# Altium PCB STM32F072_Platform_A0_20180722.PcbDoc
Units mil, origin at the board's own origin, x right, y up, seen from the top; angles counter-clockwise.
Board outline 3937.01 x 3937.01 mil, 2 copper layers (Top Layer, Bottom Layer); 126 components, 110 nets, 444 pads, 50 vias.
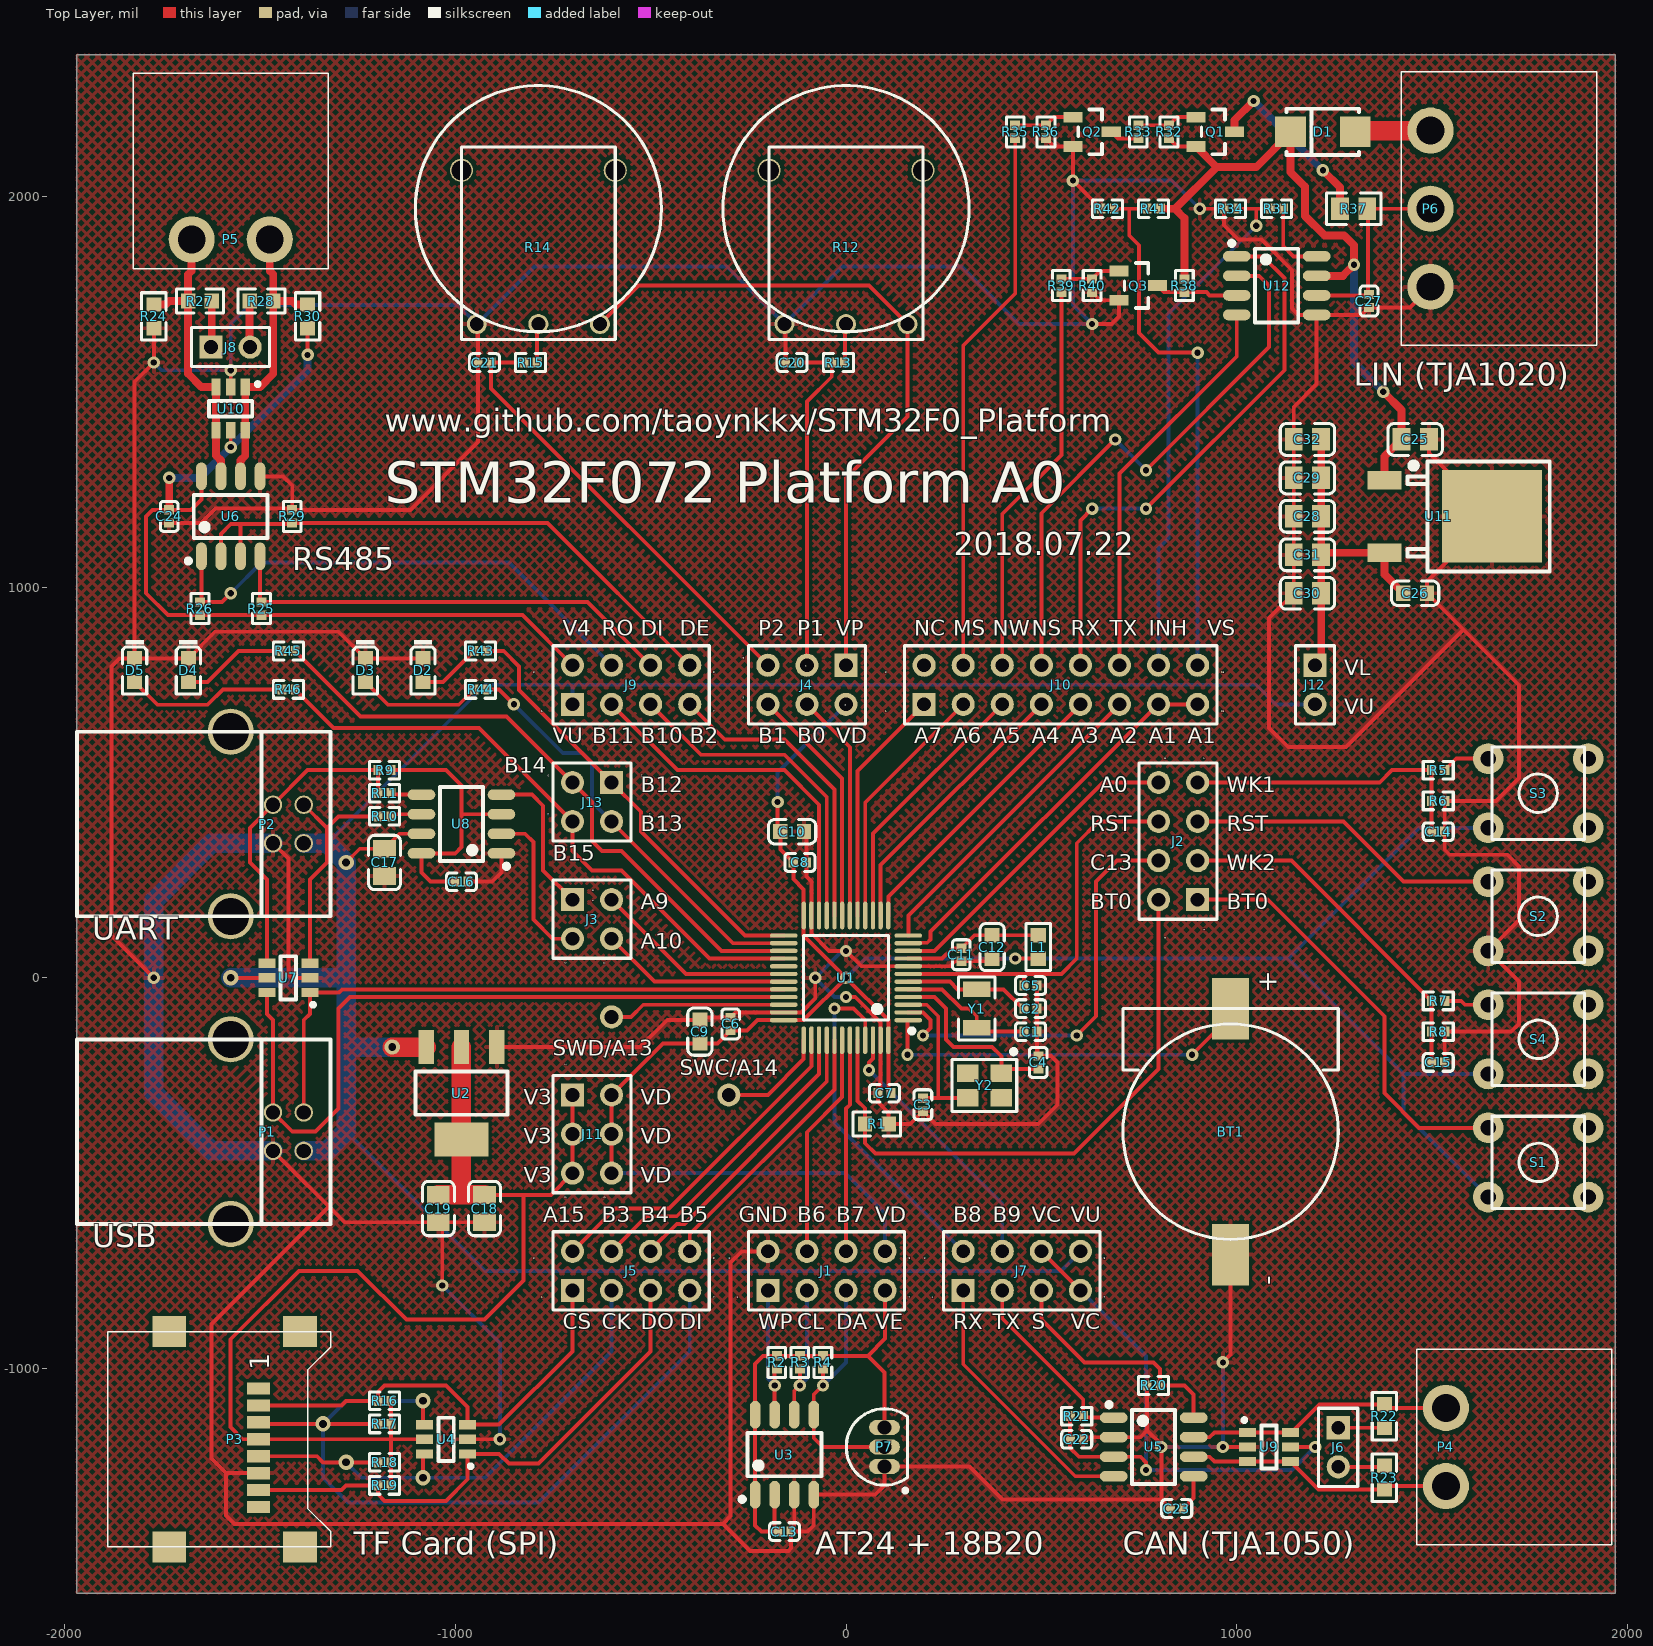
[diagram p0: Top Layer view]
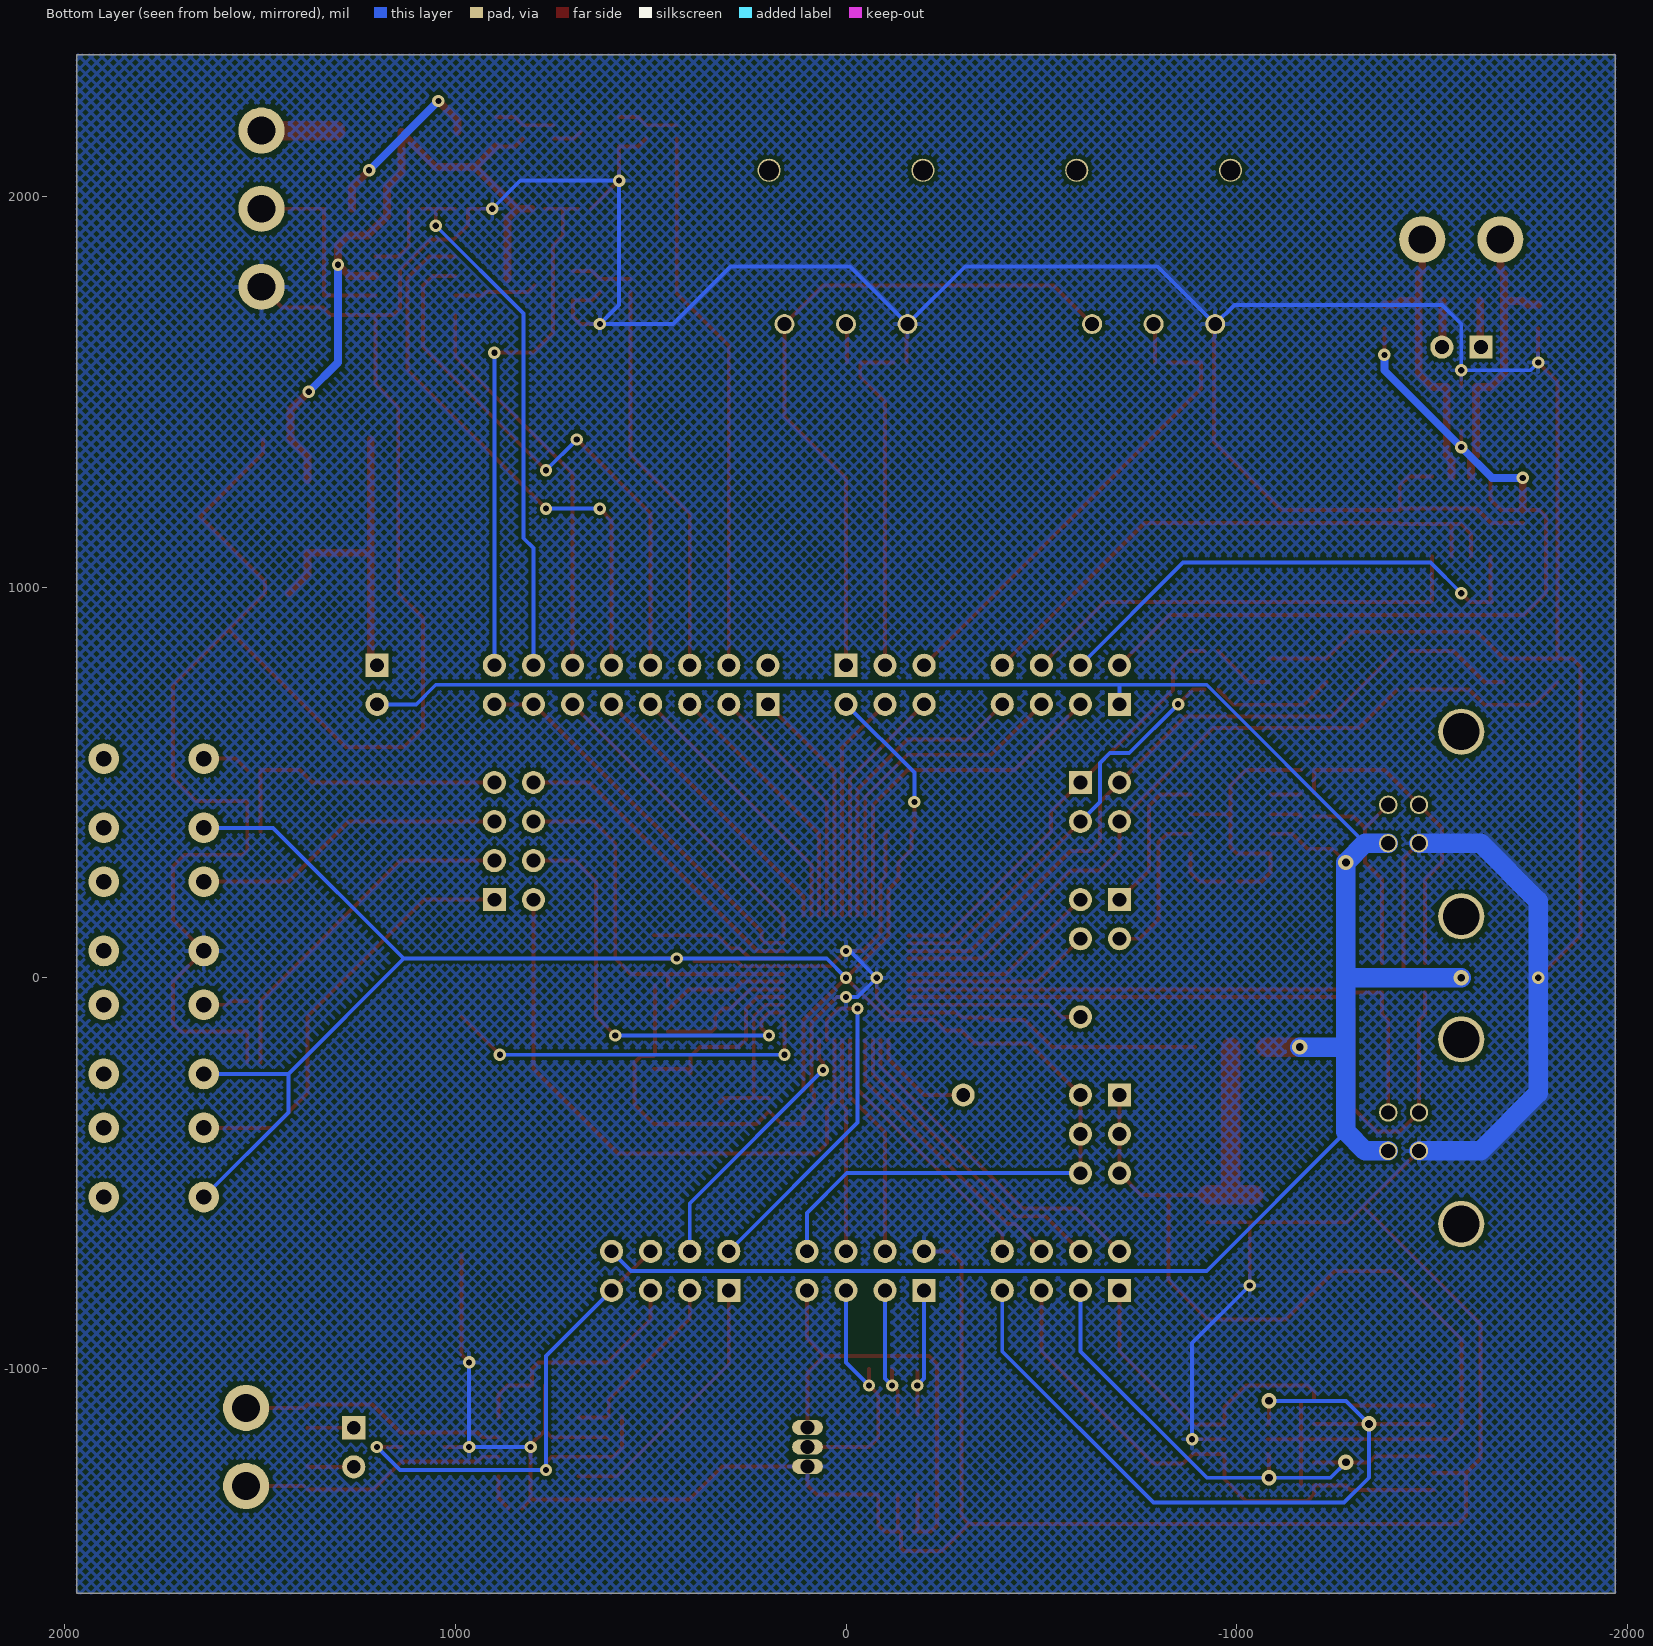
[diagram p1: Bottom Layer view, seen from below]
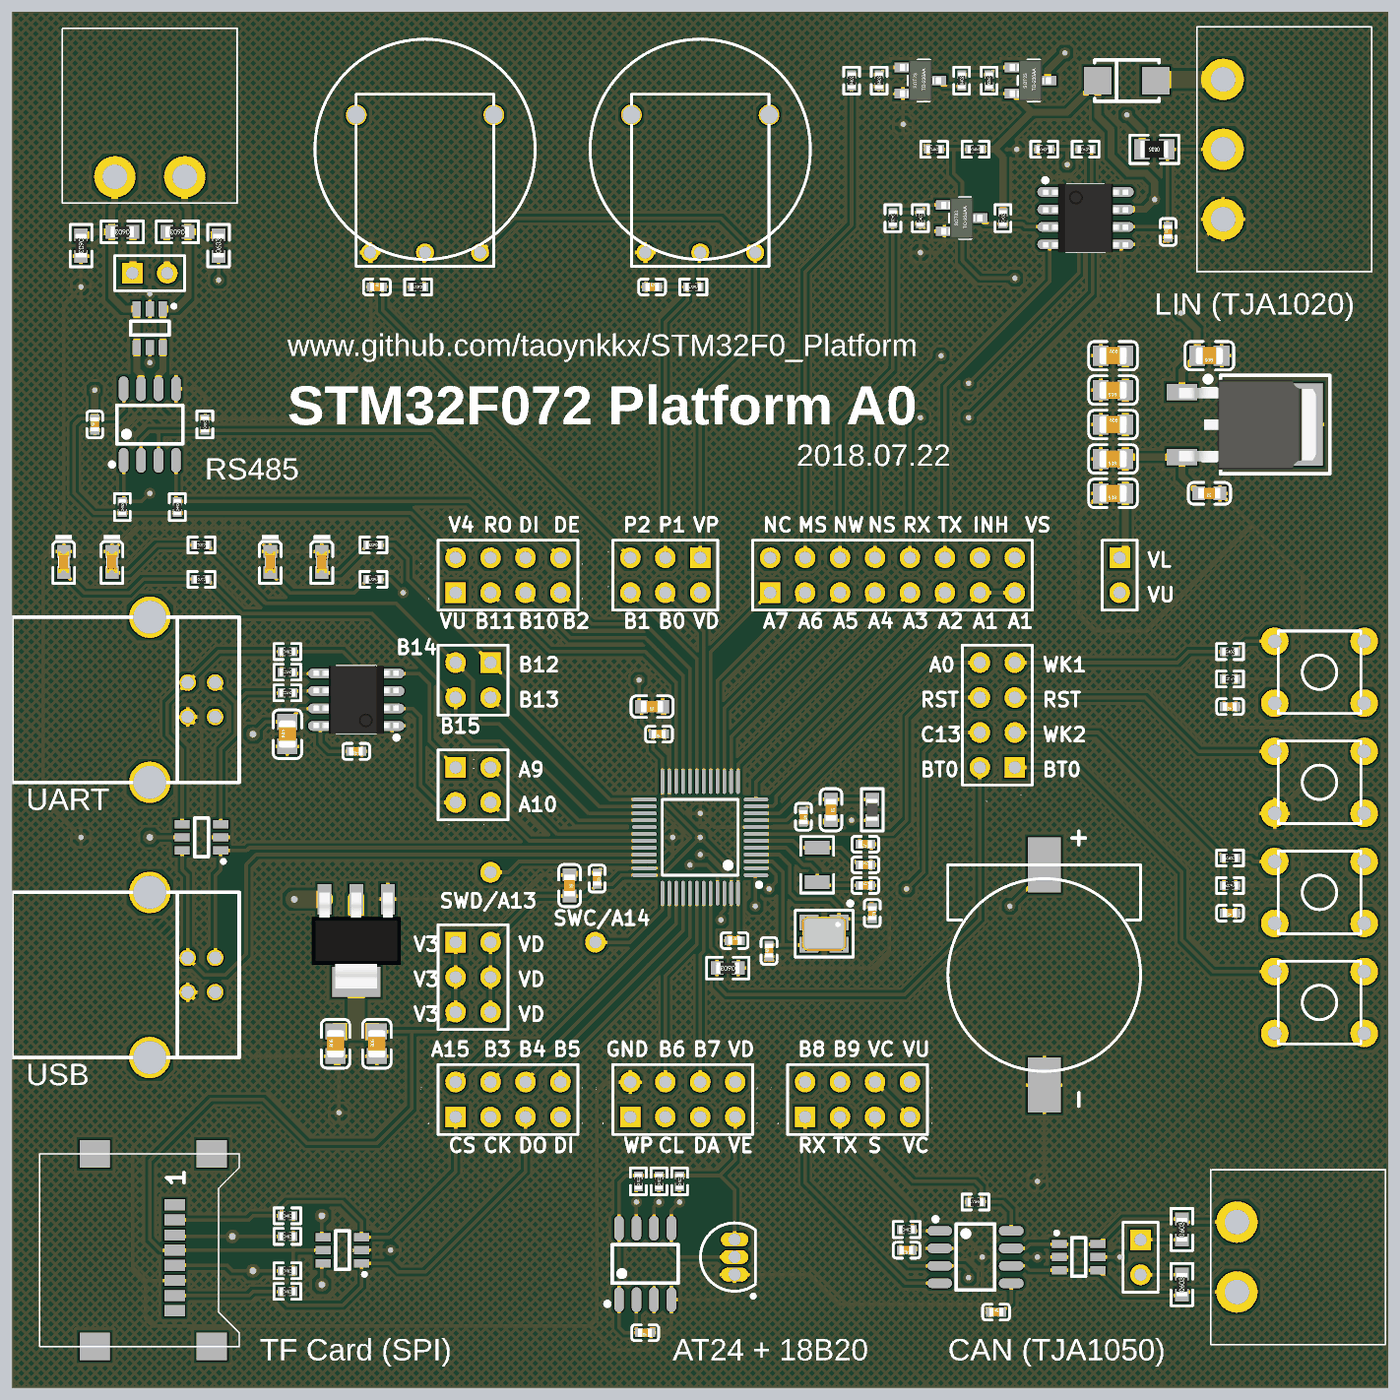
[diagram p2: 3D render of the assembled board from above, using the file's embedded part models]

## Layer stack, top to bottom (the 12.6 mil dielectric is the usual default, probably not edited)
Top Layer: signal copper 1.4
Dielectric: dielectric 12.6, FR-4, Dk 4.8
Bottom Layer: signal copper 1.4

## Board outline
-1968.5,-1574.8 -1968.5,2362.2 1968.5,2362.2 1968.5,-1574.8

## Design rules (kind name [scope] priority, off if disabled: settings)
Clearance [All] p1: gap=8
MinimumSolderMaskSliver [All] p1 off: minsoldermaskwidth=10
PolygonConnect [All] p1: connectstyle=Relief reliefconductorwidth=10 reliefentries=4 polygonreliefangle="90 Angle"
RoomDefinition LED [InComponentClass('LED')] p1: confinementstyle=ConfineIn formatcopy=TRUE lockcomponents=TRUE outline -2047.24,590.55 -787.4,590.55 -787.4,984.25 -2047.24,984.25
RoomDefinition LIN [InComponentClass('LIN')] p2: confinementstyle=ConfineIn formatcopy=TRUE lockcomponents=TRUE outline 393.7,787.4 1968.5,787.4 1968.5,2362.2 393.7,2362.2
RoomDefinition 485 [InComponentClass('485')] p3: confinementstyle=ConfineIn formatcopy=TRUE lockcomponents=TRUE outline -1181.1,787.4 -1181.1,2362.2 -1968.5,2362.2 -1968.5,787.4
RoomDefinition CAN [InComponentClass('CAN')] p4: confinementstyle=ConfineIn formatcopy=TRUE lockcomponents=TRUE outline 393.7,-1476.38 1968.5,-1476.38 1968.5,-925.2 393.7,-925.2
RoomDefinition SPI [InComponentClass('SPI')] p5: confinementstyle=ConfineIn formatcopy=TRUE lockcomponents=TRUE outline -1968.5,-1574.8 -590.55,-1574.8 -590.55,-787.4 -1968.5,-787.4
RoomDefinition ADC [InComponentClass('ADC')] p6: confinementstyle=ConfineIn formatcopy=TRUE lockcomponents=TRUE outline -1181.1,1377.95 393.7,1377.95 393.7,2362.2 -1181.1,2362.2
RoomDefinition USB [InComponentClass('USB')] p7: confinementstyle=ConfineIn formatcopy=TRUE lockcomponents=TRUE outline -787.4,-787.4 -787.4,787.4 -2165.35,787.4 -2165.35,-787.4
RoomDefinition BTN [InComponentClass('BTN')] p8: confinementstyle=ConfineIn formatcopy=TRUE lockcomponents=TRUE outline 1377.95,-629.92 1968.5,-629.92 1968.5,629.92 1377.95,629.92
RoomDefinition MCU [InComponentClass('MCU')] p9: confinementstyle=ConfineIn formatcopy=TRUE lockcomponents=TRUE outline -590.55,-590.55 590.55,-590.55 590.55,590.55 -590.55,590.55
RoomDefinition EEPROM [InComponentClass('EEPROM')] p10: confinementstyle=ConfineIn formatcopy=TRUE lockcomponents=TRUE outline -295.28,-905.51 -295.28,-1476.38 196.85,-1476.38 196.85,-905.51
RoutingVias [All] p1: holewidth=28 width=50 viastyle="Through Hole" minholewidth=28 minwidth=50 maxholewidth=28 maxwidth=50
SilkToSilkClearance [All] p1 off: silktosilkclearance=10
SilkscreenOverComponentPads [All] p1 off: minsilkscreentomaskgap=10
SolderMaskExpansion [All] p1: expansion=4
Width [All] p1: maxlimit=50 minlimit=10 preferedwidth=10
25 further rules are at their usual default settings.

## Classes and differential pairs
component class LED: D2 D3 D4 D5 R43 R44 R45 R46
component class LIN: C25 C26 C27 C28 C29 C30 C31 C32 D1 P6 Q1 Q2 Q3 R31 R32 R33 R34 R35 R36 R37 R38 R39 R40 R41 R42 U11 U12
component class CAN: C22 C23 J6 P4 R20 R21 R22 R23 U5 U9
component class ADC: C20 C21 R12 R13 R14 R15
component class STM32F072_Platform: BT1 J1 J2 J3 J4 J5 J7 J9 J10 J11 J12 J13
component class USB: C16 C17 C18 C19 P1 P2 R9 R10 R11 U2 U7 U8
component class BTN: C14 C15 R5 R6 R7 R8 S1 S2 S3 S4
component class EEPROM: C13 P7 R2 R3 R4 U3
component class MCU: C1 C2 C3 C4 C5 C6 C7 C8 C9 C10 C11 C12 L1 R1 U1 Y1 Y2
component class SPI: P3 R16 R17 R18 R19 U4
component class 485: C24 J8 P5 R24 R25 R26 R27 R28 R29 R30 U6 U10

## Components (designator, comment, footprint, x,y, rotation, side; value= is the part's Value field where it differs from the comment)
BT1 "Battery" CR1220 984.25,-393.7 r90 top
C1 "12pF (120) 5% 50V" 0402_C 472.44,-137.8 r0 top
C2 "12pF (120) 5% 50V" 0402_C 472.44,-78.74 r0 top
C3 "20pF (200) 5% 50V" 0402_C 196.85,-324.8 r90 top
C4 "20pF (200) 5% 50V" 0402_C 492.13,-216.54 r270 top
C5 "100nF (104) 10% 16V" 0402_C 472.44,-19.69 r180 top
C6 "100nF (104) 10% 16V" 0402_C -295.28,-118.11 r270 top
C7 "100nF (104) 10% 16V" 0402_C 98.43,-295.28 r0 top
C8 "100nF (104) 10% 16V" 0402_C -118.11,295.28 r180 top
C9 "4.7uF (475) 10% 16V" 0603_C -374.02,-137.8 r270 top
C10 "4.7uF (475) 10% 16V" 0603_C -137.8,374.02 r180 top
C11 "10nF (103) 10% 50V" 0402_C 295.28,59.06 r270 top
C12 "1uF (105) 10% 50V" 0603_C 374.02,78.74 r270 top
C13 "100nF (104) 10% 16V" 0402_C -157.48,-1417.32 r180 top
C14 "100nF (104) 10% 16V" 0402_C 1515.75,374.02 r180 top
C15 "100nF (104) 10% 16V" 0402_C 1515.75,-216.54 r180 top
C16 "100nF (104) 10% 16V" 0402_C -984.25,246.06 r180 top
C17 "10uF (106) 10% 25V" 0805_C -1181.1,295.28 r90 top
C18 "10uF (106) 10% 25V" 0805_C -925.2,-590.55 r90 top
C19 "10uF (106) 10% 25V" 0805_C -1043.31,-590.55 r90 top
C20 "100nF (104) 10% 16V" 0402_C -137.8,1574.8 r0 top
C21 "100nF (104) 10% 16V" 0402_C -925.2,1574.8 r0 top
C22 "100nF (104) 10% 16V" 0402_C 590.55,-1181.1 r180 top
C23 "100nF (104) 10% 16V" 0402_C 846.46,-1358.27 r0 top
C24 "100nF (104) 10% 16V" 0402_C -1732.28,1181.1 r90 top
C25 "2.2uF (225) 20% 50V" 0805_C 1456.69,1377.95 r180 top
C26 "1uF (105) 10% 50V" 0603_C 1456.69,984.25 r180 top
C27 "220pF (221) 10% 50V" 0402_C 1338.58,1732.28 r90 top
C28 "22uF (226) 20% 25V" 0805_C 1181.1,1181.1 r0 top
C29 "22uF (226) 20% 25V" 0805_C 1181.1,1279.53 r180 top
C30 "22uF (226) 20% 25V" 0805_C 1181.1,984.25 r180 top
C31 "22uF (226) 20% 25V" 0805_C 1181.1,1082.68 r180 top
C32 "22uF (226) 20% 25V" 0805_C 1181.1,1377.95 r0 top
D1 "M7" SMA(DO-214AC)_S1 1220.47,2165.35 r0 top
D2 "红灯 0603" 0603_LED_S1 -1082.68,787.4 r270 top
D3 "绿灯 0603" 0603_LED_S1 -1230.32,787.4 r270 top
D4 "蓝灯 0603" 0603_LED_S1 -1683.07,787.4 r270 top
D5 "黄灯 0603" 0603_LED_S1 -1820.87,787.4 r270 top
J1 "EEPROM" HDR2X4 -200,-800 r0 top
J2 "BUTTON" HDR2X4 900,200 r90 top
J3 "USART1" HDR2X2 -700,200 r270 top
J4 "POTMETER" HDR2X3 0,800 r180 top
J5 "TFCard" HDR2X4 -700,-800 r0 top
J6 "TERM" HDR1X2 1259.84,-1151.57 r270 top
J7 "CAN" HDR2X4 300,-800 r0 top
J8 "TERM_485" HDR1X2 -1625,1614.17 r0 top
J9 "485" HDR2X4 -700,700 r0 top
J10 "LIN" HDR2X8 200,700 r0 top
J11 "VDD" HDR2X3 -700,-300 r270 top
J12 "V5" HDR1X2 1200,800 r270 top
J13 "LED" HDR2X2 -600,500 r180 top
L1 "47nH" 0603_L 492.13,78.74 r90 top
P1 "USB_ST" USB-B/Female -1574.8,-393.7 r270 top
P2 "USB_PL" USB-B/Female -1574.8,393.7 r270 top
P3 "TFCard" TF002 -1870.08,-1181.1 r90 top
P4 "CAN" WJ2EDGRC-5.08-2PxxR 1535.43,-1200.79 r90 top
P5 "485" WJ2EDGRC-5.08-2PxxR -1574.8,1889.76 r180 top
P6 "LIN" WJ2EDGRC-5.08-3PxxR 1496.06,1968.5 r90 top
P7 "DS18B20" TO-92A 98.43,-1200.79 r0 top
Q1 "MMBT5401 2L" SOT-23(SOT-23-3) 944.88,2165.35 r180 top
Q2 "MMBT5551  G1" SOT-23(SOT-23-3) 629.92,2165.35 r180 top
Q3 "SS8050 Y1" SOT-23(SOT-23-3) 748.03,1771.65 r180 top
R1 "10KΩ (1002) ±1%" 0603_R 78.74,-374.02 r180 top
R2 "10KΩ (1002) ±1%" 0402_R -177.17,-984.25 r90 top
R3 "4.7KΩ (4701) ±1%" 0402_R -118.11,-984.25 r90 top
R4 "4.7KΩ (4701) ±1%" 0402_R -59.06,-984.25 r90 top
R5 "1KΩ (1001) ±1%" 0402_R 1515.75,531.5 r0 top
R6 "10KΩ (1002) ±1%" 0402_R 1515.75,452.76 r180 top
R7 "1KΩ (1001) ±1%" 0402_R 1515.75,-59.06 r0 top
R8 "10KΩ (1002) ±1%" 0402_R 1515.75,-137.8 r180 top
R9 "1.5KΩ (1501) ±1%" 0402_R -1181.1,531.5 r0 top
R10 "22Ω (22R0) ±1%" 0402_R -1181.1,413.39 r180 top
R11 "22Ω (22R0) ±1%" 0402_R -1181.1,472.44 r180 top
R12 "10K" AIN16 0,1968.5 r0 top
R13 "100Ω (1000) ±1%" 0402_R -19.69,1574.8 r180 top
R14 "10K" AIN16 -787.4,1968.5 r0 top
R15 "100Ω (1000) ±1%" 0402_R -807.09,1574.8 r180 top
R16 "10KΩ (1002) ±1%" 0402_R -1181.1,-1082.68 r0 top
R17 "10KΩ (1002) ±1%" 0402_R -1181.1,-1141.73 r0 top
R18 "10KΩ (1002) ±1%" 0402_R -1181.1,-1240.16 r0 top
R19 "10KΩ (1002) ±1%" 0402_R -1181.1,-1299.21 r0 top
R20 "10KΩ (1002) ±1%" 0402_R 787.4,-1043.31 r180 top
R21 "10KΩ (1002) ±1%" 0402_R 590.55,-1122.05 r0 top
R22 "68Ω (68R0) ±1%" 0603_R 1377.95,-1122.05 r90 top
R23 "68Ω (68R0) ±1%" 0603_R 1377.95,-1279.53 r90 top
R24 "470Ω (4700) ±1%" 0603_R -1771.65,1692.91 r270 top
R25 "10KΩ (1002) ±1%" 0402_R -1496.06,944.88 r90 top
R26 "10KΩ (1002) ±1%" 0402_R -1653.54,944.88 r90 top
R27 "68Ω (68R0) ±1%" 0603_R -1653.54,1732.28 r180 top
R28 "68Ω (68R0) ±1%" 0603_R -1496.06,1732.28 r180 top
R29 "10KΩ (1002) ±1%" 0402_R -1417.32,1181.1 r90 top
R30 "470Ω (4700) ±1%" 0603_R -1377.95,1692.91 r90 top
R31 "10KΩ (1002) ±1%" 0402_R 1102.36,1968.5 r0 top
R32 "10KΩ (1002) ±1%" 0402_R 826.77,2165.35 r270 top
R33 "1KΩ (1001) ±1%" 0402_R 748.03,2165.35 r90 top
R34 "1KΩ (1001) ±1%" 0402_R 984.25,1968.5 r0 top
R35 "1KΩ (1001) ±1%" 0402_R 433.07,2165.35 r90 top
R36 "10KΩ (1002) ±1%" 0402_R 511.81,2165.35 r90 top
R37 "1KΩ (1001) ±1%" 0805_R 1299.21,1968.5 r180 top
R38 "10KΩ (1002) ±1%" 0402_R 866.14,1771.65 r90 top
R39 "1KΩ (1001) ±1%" 0402_R 551.18,1771.65 r270 top
R40 "10KΩ (1002) ±1%" 0402_R 629.92,1771.65 r90 top
R41 "10KΩ (1002) ±1%" 0402_R 787.4,1968.5 r0 top
R42 "1KΩ (1001) ±1%" 0402_R 669.29,1968.5 r0 top
R43 "1KΩ (1001) ±1%" 0402_R -935.04,836.61 r180 top
R44 "1KΩ (1001) ±1%" 0402_R -935.04,738.19 r180 top
R45 "1KΩ (1001) ±1%" 0402_R -1427.17,836.61 r180 top
R46 "1KΩ (1001) ±1%" 0402_R -1427.17,738.19 r180 top
S1 "BOOT" SW-6x6 1771.65,-472.44 r270 top
S2 "RESET" SW-6x6 1771.65,157.48 r270 top
S3 "WK1" SW-6x6 1771.65,472.44 r270 top
S4 "WK2" SW-6x6 1771.65,-157.48 r270 top
U1 "STM32F072C8T6" LQFP-48_7x7x05P 0,0 r90 top
U2 "AMS1117-3.3" SOT-223 -984.25,-295.28 r90 top
U3 "EEPROM/AT24C256C-SSHL-T" SOIC-8_150mil -157.48,-1220.47 r0 top
U4 "SRV05-4-P-T7" SOT-23-6 -1023.62,-1181.1 r0 top
U5 "CAN/TJA1050T/CM" SOIC-8_150mil 787.4,-1200.79 r270 top
U6 "SP485EEN-L/TR" SOIC-8_150mil -1574.8,1181.1 r0 top
U7 "SRV05-4-P-T7" SOT-23-6 -1427.17,0 r0 top
U8 "PL2303SA" SOP-8_150mil -984.25,393.7 r90 top
U9 "SRV05-4-P-T7" SOT-23-6 1082.68,-1200.79 r180 top
U10 "SRV05-4-P-T7" SOT-23-6 -1574.8,1456.69 r90 top
U11 "L78M05ABDT-TR" TO-252-2-180 1377.95,1181.1 r0 top
U12 "TJA1020" SOP-8_150mil 1102.36,1771.65 r270 top
Y1 "32.768KHz ±20ppm 12.5pF" "SMD-3215_2P FC - 135" 334.65,-78.74 r270 top
Y2 "12MHZ 20PF 10PPM" SMD-3225_4P 354.33,-275.59 r180 top

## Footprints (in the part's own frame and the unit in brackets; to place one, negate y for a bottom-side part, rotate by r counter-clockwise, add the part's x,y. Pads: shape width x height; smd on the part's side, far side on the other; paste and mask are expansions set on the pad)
0402_C [mm]
  rect 0.6x0.65 smd mask+0.051: 1(-0.425,0) 2(0.425,0)
  silkscreen extent -0.97,-0.58 0.97,0.58, body extent -0.48,-0.3 0.52,0.3, height 0.2
0402_R [mm]
  rect 0.6x0.65 smd mask+0.051: 1(-0.425,0) 2(0.425,0)
  silkscreen extent -0.97,-0.58 0.97,0.58, body extent -0.57,-0.27 0.58,0.28, height 0.41
0603_C [mm]
  rect 0.93x0.98 smd: 1(-0.77,0) 2(0.77,0)
  silkscreen extent -1.53,-0.79 1.54,0.79, body extent -0.8,-0.4 0.8,0.4, height 0.3
0603_L [mm]
  rect 0.93x0.98 smd: 1(-0.77,0) 2(0.77,0)
  silkscreen extent -1.53,-0.79 1.54,0.79, body extent -0.82,-0.41 0.83,0.41, height 0.46
0603_LED_S1 [mm]
  rect 0.93x0.98 smd: A(0.77,0) K(-0.77,0)
  silkscreen extent -1.97,-0.79 1.54,0.79, body extent -0.8,-0.4 0.8,0.4, height 0.6
0603_R [mm]
  rect 0.93x0.98 smd: 1(-0.77,0) 2(0.77,0)
  silkscreen extent -1.53,-0.79 1.54,0.79, body extent -0.85,-0.4 0.85,0.4, height 0.56
0805_C [mm]
  rect 1.16x1.47 smd: 1(-0.89,0) 2(0.89,0)
  silkscreen extent -1.77,-1.04 1.77,1.04, body extent -1,-0.62 1,0.63, height 0.77
0805_R [mm]
  rect 1.16x1.47 smd: 1(-0.89,0) 2(0.89,0)
  silkscreen extent -1.77,-1.04 1.77,1.03, body extent -1,-0.62 1,0.63, height 0.49
AIN16 [mm]
  round 1.5 hole 1.3: 0(-5,2.5) 0(5,2.5)
  round 1.3 hole 0.9: 1(-4,-7.5) 2(4,-7.5) 3(0,-7.5)
  silkscreen extent -8,-8.5 8,8, body extent -7.94,-8.5 8,7.98, height 4
CR1220 [mm]
  rect 4x2.4 smd: 1(8,0) 2(-8,0)
  silkscreen extent -7,-7 8,7, body extent -6.94,-6.99 7,6.99, height 4
HDR1X2 [mm] "Connector; Header; 2 Position"
  rect 1.5x1.5 hole 0.9: 1(0,0)
  round 1.5 hole 0.9: 2(2.54,0)
  silkscreen extent -1.27,-1.27 3.81,1.27
HDR2X2 [mm] "Connector; Header; 2x2 Position"
  rect 1.5x1.5 hole 0.9: 1(0,0)
  round 1.5 hole 0.9: 2(0,2.54) 3(2.54,0) 4(2.54,2.54)
  silkscreen extent -1.27,-1.27 3.81,3.81
HDR2X3 [mm] "Connector; Header; 3x2 Position"
  rect 1.5x1.5 hole 0.9: 1(0,0)
  round 1.5 hole 0.9: 2(0,2.54) 3(2.54,0) 4(2.54,2.54) 5(5.08,0) 6(5.08,2.54)
  silkscreen extent -1.27,-1.27 6.35,3.81
HDR2X4 [mm] "Connector; Header; 4x2 Position"
  rect 1.5x1.5 hole 0.9: 1(0,0)
  round 1.5 hole 0.9: 2(0,2.54) 3(2.54,0) 4(2.54,2.54) 5(5.08,0) 6(5.08,2.54) 7(7.62,0) 8(7.62,2.54)
  silkscreen extent -1.27,-1.27 8.89,3.81
HDR2X8 [mm] "Connector; Header; 8x2 Position"
  rect 1.5x1.5 hole 0.9: 1(0,0)
  round 1.5 hole 0.9: 2(0,2.54) 3(2.54,0) 4(2.54,2.54) 5(5.08,0) 6(5.08,2.54) 7(7.62,0) 8(7.62,2.54) 9(10.16,0) 10(10.16,2.54) 11(12.7,0) 12(12.7,2.54) 13(15.24,0) 14(15.24,2.54) 15(17.78,0) 16(17.78,2.54)
  silkscreen extent -1.27,-1.27 19.05,3.81
LQFP-48_7x7x05P [mm]
  oval 0.28x1.8 smd mask+0.051: 1(-2.75,-4.05) 2(-2.25,-4.05) 3(-1.75,-4.05) 4(-1.25,-4.05) 5(-0.75,-4.05) 6(-0.25,-4.05) 7(0.25,-4.05) 8(0.75,-4.05) 9(1.25,-4.05) 10(1.75,-4.05) 11(2.25,-4.05) 12(2.75,-4.05) 25(2.75,4.05) 26(2.25,4.05) 27(1.75,4.05) 28(1.25,4.05) 29(0.75,4.05) 30(0.25,4.05) 31(-0.25,4.05) 32(-0.75,4.05) 33(-1.25,4.05) 34(-1.75,4.05) 35(-2.25,4.05) 36(-2.75,4.05)
  oval 1.8x0.28 smd mask+0.051: 13(4.05,-2.75) 14(4.05,-2.25) 15(4.05,-1.75) 16(4.05,-1.25) 17(4.05,-0.75) 18(4.05,-0.25) 19(4.05,0.25) 20(4.05,0.75) 21(4.05,1.25) 22(4.05,1.75) 23(4.05,2.25) 24(4.05,2.75) 37(-4.05,2.75) 38(-4.05,2.25) 39(-4.05,1.75) 40(-4.05,1.25) 41(-4.05,0.75) 42(-4.05,0.25) 43(-4.05,-0.25) 44(-4.05,-0.75) 45(-4.05,-1.25) 46(-4.05,-1.75) 47(-4.05,-2.25) 48(-4.05,-2.75)
  silkscreen extent -3.6,-4.43 2.75,2.75
SMA(DO-214AC)_S1 [mm]
  rect 2x2 smd: 1(2.1,0) 2(-2.1,0)
  silkscreen extent -2.35,-1.5 2.35,1.5
"SMD-3215_2P FC - 135" [mm]
  rect 1x1.8 smd: 1(-1.25,0) 2(1.25,0)
  silkscreen extent -2.05,-1.2 2.05,1.2
SMD-3225_4P [mm]
  rect 1.4x1.15 smd: 1(-1.1,-0.8) 2(1.1,-0.8) 3(1.1,0.8) 4(-1.1,0.8)
  silkscreen extent -2.1,-2.35 2.1,1.7, body extent -1.6,-1.25 1.6,1.25, height 0.61
SOIC-8_150mil [mm]
  oval 0.7x1.8 smd: 1(-1.905,-2.6) 2(-0.635,-2.6) 3(0.635,-2.6) 4(1.905,-2.6) 5(1.905,2.6) 6(0.635,2.6) 7(-0.635,2.6) 8(-1.905,2.6)
  silkscreen extent -2.9,-3.05 2.4,1.4
SOP-8_150mil [mm]
  oval 0.7x1.8 smd: 1(-1.905,-2.6) 2(-0.635,-2.6) 3(0.635,-2.6) 4(1.905,-2.6) 5(1.905,2.6) 6(0.635,2.6) 7(-0.635,2.6) 8(-1.905,2.6)
  silkscreen extent -2.9,-3.08 2.4,1.4, body extent -2.5,-3.1 2.5,3.1, height 1.75
SOT-23(SOT-23-3) [mm]
  rect 1.25x0.7 smd: 1(1.25,-0.95) 2(1.25,0.95) 3(-1.25,0)
  silkscreen extent -0.65,-1.46 0.9,1.46, body extent -1.5,-1.5 1.5,1.5, height 1.3
SOT-23-6 [mm]
  rect 1.1x0.6 smd: 1(1.4,-0.95) 2(1.4,0) 3(1.4,0.95) 4(-1.4,0.95) 5(-1.4,0) 6(-1.4,-0.95)
  silkscreen extent -0.5,-1.87 1.73,1.4
SOT-223 [mm]
  rect 2.2x1 smd: 1(3,-2.3) 2(3,0) 3(3,2.3)
  rect 2.2x3.5 smd: 2(-3,0)
  silkscreen extent -1.4,-3 1.4,3, body extent -3.49,-3.24 3.49,3.24, height 1.64
SW-6x6 [mm]
  round 2 hole 1: 1(-2.25,-3.25) 2(2.25,-3.25) 3(2.25,3.25) 4(-2.25,3.25)
  silkscreen extent -3,-3 3,3, body extent -3,-3 3,3, height 8
TF002 [mm]
  rect 2x2.2 smd: 0(-7,-3.5) 0(-7,-12) 0(7,-3.5) 0(7,-12)
  rect 0.8x1.5 smd: 1(3.3,-9.3) 2(2.2,-9.3) 3(1.1,-9.3) 4(0,-9.3) 5(-1.1,-9.3) 6(-2.2,-9.3) 7(-3.3,-9.3) 8(-4.4,-9.3)
  silkscreen extent -7,-14 7,0.5, body extent -7,-14 7,0.5, height 2
TO-92A [mm] "TO, Flat Index; 3 In-Line, Axial Leads; Body Dia. 4.5mm; Leads 0.51 x 0.48 mm (max)"
  oval 2x1 hole 0.9: 1(0,-1.27) 2(0,0) 3(0,1.27)
  silkscreen extent -2.48,-2.95 1.5,2.48, body extent -2.5,-2.5 1.5,2.5, height 6.86
TO-252-2-180 [mm]
  rect 2.2x1.2 smd: 1(0,2.361) 3(0.004,-2.361)
  rect 6.5x6 smd: 2(7,0)
  silkscreen extent 1.5,-3.57 10.75,3.57, body extent -0.2,-3.27 9.74,3.27, height 2.44
USB-B/Female [mm]
  round 1.2 hole 0.92: 1(1.25,4.75) 2(-1.25,4.75) 3(-1.25,2.75) 4(1.25,2.75)
  round 3 hole 2.4: 5(-6,0) 6(6,0)
  silkscreen extent -6,-10 6,6.5, body extent -6,-10 6,6.5, height 10.8
WJ2EDGRC-5.08-2PxxR [mm]
  round 3 hole 1.8: 1(-2.54,0) 2(2.54,0)
  silkscreen extent -6.35,-10.79 6.35,1.91, body extent -6.35,-10.79 6.35,1.91, height 8.5
WJ2EDGRC-5.08-3PxxR [mm]
  round 3 hole 1.8: 1(-5.08,0) 2(0,0) 3(5.08,0)
  silkscreen extent -8.89,-10.79 8.89,1.91, body extent -8.89,-10.79 8.89,1.91, height 8.5

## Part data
BT1: "Multicell Battery"
C1 C2: library part "0402 12pF (120) 5% 50V", "贴片"
C3 C4: library part "0402 20pF (200) 5% 50V", "贴片"
C5 C6 C7 C8 C13 C14 C15 C16 C20 C21 C22 C23 C24: library part "0402 100nF (104) 10% 16V", "贴片"
C9 C10: library part "0603 4.7uF (475) 10% 16V", "贴片"
C11: library part "0402 10nF (103) 10% 50V", "贴片"
C12 C26: library part "0603 1uF (105) 10% 50V", "贴片"
C17 C18 C19: library part "0805 10uF (106) 10% 25V", "贴片"
C25: library part "0805 2.2uF (225) 20% 50V", "贴片"
C27: library part "0402 220pF (221) 10% 50V", "贴片"
C28 C29 C30 C31 C32: library part "0805 22uF (226) 20% 25V", "贴片"
D1: library part "SMA(DO-214AC) M7", "¶þ¼"
D2: library part "0603 红灯", "·"
D3: library part "0603 绿灯", "·"
D4: library part "0603 蓝灯", "·"
D5: library part "0603 黄灯", "·"
J1 J2 J5 J7 J9: library part "Header 4X2", "Header, 4-Pin, Dual row"
J3: library part "Header 2X2", "Header, 2-Pin, Dual row"
J4: library part "Header 3X2", "POT"
J6 J8 J12 P4 P5: library part "Header 2", "Header, 2-Pin"
J10: library part "Header 8X2", "Header, 8-Pin, Dual row"
J11: library part "Header 3X2", "Header, 3-Pin, Dual row"
J13: library part "Header 4", "Header, 4-Pin"
L1: library part "0603 47nH", "贴片"
P1 P2: library part USB-B/Female, "USB-B/Female"
P3: library part "Header 8", "Header, 8-Pin"
P6 P7: library part "Header 3", "Header, 3-Pin"
Q1: library part "SOT-23 MMBT5401 2L", "Èý¼"
Q2: library part "SOT-23 MMBT5551  G1", "Èý¼"
Q3: library part "SOT-23 SS8050 Y1", "Èý¼"
R1: library part "0603 10KΩ (1002) 1%", "贴"
R2 R6 R8 R16 R17 R18 R19 R20 R21 R25 R26 R29 R31 R32 R36 R38 R40 R41: library part "0402 10KΩ (1002) 1%", "贴"
R3 R4: library part "0402 4.7KΩ (4701) 1%", "贴"
R5 R7 R33 R34 R35 R39 R42 R43 R44 R45 R46: library part "0402 1KΩ (1001) 1%", "贴"
R9: library part "0402 1.5KΩ (1501) 1%", "贴"
R10 R11: library part "0402 22Ω (22R0) 1%", "贴"
R12 R14: library part "Res Tap", "Tapped Resistor"
R13 R15: library part "0402 100Ω (1000) 1%", "贴"
R22 R23 R27 R28: library part "0603 68Ω (68R0) 1%", "贴"
R24 R30: library part "0603 470Ω (4700) 1%", "贴"
R37: library part "0805 1KΩ (1001) 1%", "贴"
S1 S2 S3 S4: library part SW-PB, "Switch"
U1: "ARM"
U2: library part "SOT-223 AMS1117-3.3", "低压差线"
U3: library part EEPROM/AT24C256C-SSHL-T_[C6482], "EEPROM"
U4 U7 U9 U10: library part SRV05-4-P-T7_[C85364], "TVS"
U5: library part CAN/TJA1050T/CM_[C6952], "CAN"
U6: library part SP485EEN-L/TR_[C6855], "RS-485/RS-422"
U11: library part "TO-252-2 L78M05ABDT-TR", "低压差线"
Y1: library part "SMD-3215_2P 32.768KHz 20ppm 12.5pF", "贴片"
Y2: library part "SMD-3225_4P  12MHZ 20PF 10PPM", "贴片"

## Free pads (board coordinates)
  round 59.06 hole 35.43: 0(-600,-100) 1(-300,-300)

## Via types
v1: diameter 31.5, hole 15.75, Top Layer to Bottom Layer, tented both sides, 43 vias
v2: diameter 39.37, hole 19.68, Top Layer to Bottom Layer, tented both sides, 7 vias

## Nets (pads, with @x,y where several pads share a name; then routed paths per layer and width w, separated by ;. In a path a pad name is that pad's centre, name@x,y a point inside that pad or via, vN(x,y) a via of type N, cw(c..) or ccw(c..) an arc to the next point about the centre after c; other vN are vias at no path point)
485_A: P5.1 R28.1 R30.2 U6.6 U10.1 U10.6 | length 758.3
  Top Layer w20: U6.6 -1549.8,1324.21 -1537.4,1336.61 U10.6 U10.1 -1500,1511.81 -1465.75,1546.06 R28.1 ; P5.1 -1474.8,1809.45 -1465.75,1800.39 R28.1 ; R30.2 -1408.27,1723.23 -1417.32,1732.28 R28.1
485_B: P5.2 R24.1 R27.2 U6.7 U10.3 U10.4 | length 758.3
  Top Layer w20: R24.1 -1741.34,1723.23 -1732.28,1732.28 R27.2 ; P5.2 -1674.8,1809.45 -1683.86,1800.39 R27.2 ; U6.7 -1599.8,1324.21 -1612.2,1336.61 U10.4 U10.3 -1649.61,1511.81 -1683.86,1546.06 R27.2
485_RX/PB11: J9.3 U1.22 | length 921.1
  Top Layer w10: J9.3 -431.5,531.5 -157.48,531.5 -68.9,442.91 U1.22
485_TX/PB10: J9.5 U1.21 | length 852.3
  Top Layer w10: J9.5 -370.87,570.87 -157.48,570.87 -49.21,462.6 U1.21
ADC_IN8/PB0: J4.4 U1.18 | length 586
  Top Layer w10: J4.4 9.84,590.16 U1.18
ADC_IN9/PB1: J4.6 U1.19 | length 619.3
  Top Layer w10: J4.6 -9.84,509.84 U1.19
BOOT: J2.1 S1.1 | length 1100.9
  Top Layer w10: J2.1 1079.53,200 1377.95,-98.43 1377.95,-295.28 1466.54,-383.86 S1.1
BOOT0: J2.2 R1.2 U1.44 | length 1557.5
  Top Layer w10: U1.44 29.53,-314.96 48.43,-333.86 R1.2 48.43,-423.43 75,-450 583.46,-450 800,-233.46 J2.2
CAN_RX/PB8: J7.2 U1.45 | length 899.9
  Top Layer w10: v1(-29.53,-78.74) 19.69,-78.74 49.21,-108.27 U1.45
  Bottom Layer w10: v1(-29.53,-78.74) -29.53,-370.47 J7.2
CAN_RXD: J7.1 U5.4 | length 692.8
  Top Layer w10: J7.1 300,-988.98 586.81,-1275.79 U5.4
CAN_TX/PB9: J7.4 U1.46 | length 685.9
  Top Layer w10: v1(59.06,-236.22) 59.06,-216.54 68.9,-206.69 U1.46
  Bottom Layer w10: v1(59.06,-236.22) 400,-577.17 J7.4
CAN_TXD: J7.3 R21.2 U5.1 | length 487.2
  Top Layer w10: J7.3 400,-872.44 607.28,-1079.72 R21.2 611.02,-1125.79 U5.1
CANH: P4.2 R22.2 U5.7 U9.1 U9.6 | length 697
  Top Layer w10: U5.7 930.51,-1175.79 942.91,-1163.39 U9.1 U9.6 1139.76,-1163.39 1211.42,-1091.73 R22.2 1387.01,-1100.79 P4.2 P4.2@1526.38,-1091.73
CANL: P4.1 R23.1 U5.6 U9.3 U9.4 | length 671.4
  Top Layer w10: U5.6 930.51,-1225.79 942.91,-1238.19 U9.3 U9.4 1209.45,-1309.84 R23.1 ; R23.1@1387.01,-1300.79 P4.1
CS: J5.1 P3.2 R16.1 U4.3 | length 1140.2
  Top Layer w10: P3.2 -1291.34,-1094.49 -1279.53,-1082.68 R16.1 -1197.83,-1060.04 -1181.1,-1043.31 -1023.62,-1043.31 -968.5,-1098.43 U4.3 -887.8,-1143.7 -700,-955.91 J5.1
DBG_RX/PA10: J3.4 U1.31 | length 486
  Top Layer w10: J3.4 -490.16,-9.84 U1.31
DBG_TX/PA9: J3.2 U1.30 | length 519.3
  Top Layer w10: J3.2 -409.84,9.84 U1.30
DI: J5.7 P3.3 R17.1 U4.4 | length 2069.9
  Top Layer w10: P3.3 -1500,-1141.73 R17.1 ; v2(-1082.68,-1082.68) -1082.68,-1139.76 U4.4
  Bottom Layer w10: v2(-1082.68,-1082.68) -1279.53,-1082.68 v2(-1338.58,-1141.73) -1338.58,-1279.53 -1274.8,-1343.31 -787.4,-1343.31 -400,-955.91 J5.7
DM: P1.2 U1.32 U7.1 | length 1529.5
  Top Layer w10: P1.2 -1387.8,-108.27 -1372.05,-92.52 U7.1 -1297.24,-37.4 -1289.37,-29.53 U1.32
DM_PL: P2.2 R10.2 U7.3 | length 591
  Top Layer w10: P2.2 -1328.74,383.86 ; U7.3 -1372.05,251.97 -1328.74,295.28 -1328.74,383.86 ; R10.2 -1299.21,413.39 -1328.74,383.86
DO: J5.5 P3.7 R19.1 U4.1 | length 1411.4
  Top Layer w10: P3.7 -1291.34,-1311.02 -1279.53,-1299.21 R19.1 -1197.83,-1321.85 -1181.1,-1338.58 -1023.62,-1338.58 -968.5,-1283.46 U4.1 -887.8,-1218.5 -862.99,-1243.31 -787.4,-1243.31 -500,-955.91 J5.5
DP: P1.3 U1.33 U7.6 | length 1933.7
  Top Layer w10: U7.6 -1482.28,-92.52 -1466.54,-108.27 P1.3 -1417.32,-393.7 -1358.27,-393.7 -1299.21,-334.65 -1299.21,-78.74 -1269.68,-49.21 U1.33
DP_PL: P2.3 R9.1 R11.2 U7.4 | length 812.4
  Top Layer w10: U7.4 -1482.28,251.97 -1525.59,295.28 -1525.59,383.86 P2.3 -1377.95,531.5 R9.1 R11.2
EEP_SCL/PB6: J1.4 U1.42 | length 577.9
  Top Layer w10: J1.4 -100,-395.28 -9.84,-305.12 U1.42
EEP_SDA/PB7: J1.6 U1.43 | length 544.6
  Top Layer w10: J1.6 0,-334.65 9.84,-324.8 U1.43
GND: BT1.2 C1.2 C2.2 C3.1 C4.1 C5.1 C6.1 C7.1 C8.1 C9.1 C10.1 C11.2 C12.2 C13.1 C14.1 C15.1 C16.1 C17.1 C18.1 C19.1 C20.1 C21.1 C22.1 C23.1 C24.1 C25.1 C26.1 C27.1 C28.1 C29.2 C30.2 C31.2 C32.1 D2.K D3.K D4.K D5.K J1.2 P1.4 P2.4 P3.6 P6.1 P7.1 Q2.2 Q3.2 R1.1 R6.1 R8.1 R12.1 R14.1 R20.2 R24.2 R29.2 R34.1 R36.1 R40.1 R42.1 S2.2 U1.8 U1.23 U1.35 U1.47 U2.1 U3.3 U3.4 U4.2 U5.2 U6.5 U7.2 U8.1 U9.2 U10.2 U11.2 U12.5 | length 24990.4
  Top Layer w10: v1(-1771.65,0) -1879.92,108.27 -1879.92,797.24 -1859.45,817.72 D5.K ; R24.2 v1(-1771.65,1574.8) -1820.87,1525.59 D5.K ; C24.1 -1650.59,1164.37 -1614.17,1200.79 -1417.32,1200.79 -1417.32,1259.84 -1440.94,1283.46 U6.5 ; U10.2 v1(-1574.8,1555.12) ; P3.6 -1586.61,-1267.72 ; P1.4 -1283.86,-625.59 C19.1 C18.1 ; P2.4 -1427.17,305.12 -1427.17,9.84 -1417.32,0 U7.2 ; R29.2 -1115.16,1197.83 -941.93,1371.06 C21.1 -941.93,1670.28 R14.1 ; -1328.74,-590.55 -1624.02,-885.83 -1624.02,-1230.32 -1586.61,-1267.72 ; D2.K D3.K -1298.43,885.83 -1614.96,885.83 D4.K D5.K ; v1(-1033.46,-787.4) C19.1@-1033.46,-635.43 ; U4.2 v1(-885.83,-1181.1) ; C16.1 -905.51,246.06 -881.89,269.68 U8.1 ; U2.1 -527.17,-177.17 -457.48,-107.48 C9.1 -367.91,-101.38 C6.1 -282.48,-88.58 U1.35 -114.04,-88.58 -78.74,-53.28 v1(-78.74,0) ; J1.2 -266.93,-700 -295.28,-728.35 -295.28,-1377.95 -314.96,-1397.64 ; R12.1 -154.53,1670.28 C20.1 ; U3.3 -132.48,-1409.06 C13.1 ; C10.1 -101.38,367.91 C8.1 -101.38,258.86 -88.58,246.06 U1.23 -88.58,114.04 -43.44,68.9 v1(0,68.9) 39.37,29.53 U1.8 265.75,29.53 278.54,42.32 C11.2 C12.2@387.6,42.32 ; v1(0,-49.21) 23.76,-49.21 88.58,-114.04 U1.47 C7.1@88.58,-288.39 ; C7.1 81.69,-317.91 109.06,-345.28 R1.1 164.37,-374.02 C3.1 229.33,-374.02 492.13,-374.02 541.34,-324.8 541.34,-216.54 524.61,-199.8 C4.1 489.17,-196.85 C1.2 C5.1 ; R36.1 532.48,2127.95 Q2.2 v1(580.71,2040.35) R42.1 ; C22.1 612.6,-1175.79 U5.2 753.35,-1175.79 770.67,-1158.46 ; v1(629.92,1673.23) 679.13,1673.23 698.82,1692.91 Q3.2 650.59,1734.25 R40.1 ; R20.2 770.67,-1158.46 ; C23.1 807.09,-1335.63 ; v1(905.51,1968.5) R34.1 967.52,1926.18 1003.94,1889.76 1062.99,1889.76 1141.73,1811.02 1141.73,1712.6 1157.68,1696.65 U12.5 ; v1(964.57,-1200.79) U9.2 ; v1(964.57,-984.25) 984.25,-964.57 BT1.2 ; C25.1 1491.73,1342.91 U11.2 1487.01,1014.57 C26.1 1722.44,748.82 1722.44,511.81 1663.39,452.76 R6.1 C14.1 1532.48,327.76 1545.28,314.96 1692.91,314.96 1722.44,285.43 1722.44,147.64 S2.2 1722.44,-9.84 1722.44,-118.11 1702.76,-137.8 R8.1 C15.1 ; P6.1 1443.11,1715.55 C27.1 1319.68,1696.65 U12.5 ; 1575.59,886.61 1279.53,590.55 1131.89,590.55 1082.68,639.76 1082.68,920.87 C30.2 C31.2 C28.1 C29.2 C32.1 1146.06,1461.02 1204.72,1519.69 U12.5 ; -1586.61,-1267.72 -1586.61,-1375.98 -1564.96,-1397.64 -314.96,-1397.64 ; -314.96,-1397.64 -246.06,-1466.54 -147.64,-1466.54 -140.75,-1459.65 C13.1 ; C13.1 -98.43,-1417.32 -82.48,-1401.38 U3.4 74.8,-1322.83 98.43,-1299.21 P7.1 315.75,-1250.79 400.59,-1335.63 807.09,-1335.63 ; 770.67,-1158.46 807.09,-1194.88 v1(807.09,-1200.79) 807.09,-1335.63
  Bottom Layer w10: v1(-1771.65,1574.8) -1751.97,1555.12 v1(-1574.8,1555.12) -1574.8,1673.23 -1525.59,1722.44 -994.09,1722.44 R14.1 -797.24,1820.87 -305.12,1820.87 R12.1 -9.84,1820.87 295.28,1820.87 442.91,1673.23 v1(629.92,1673.23) 580.71,1722.44 v1(580.71,2040.35) 833.66,2040.35 v1(905.51,1968.5) ; v1(-1033.46,-787.4) -885.83,-935.04 v1(-885.83,-1181.1) ; v1(0,-49.21) -29.53,-49.21 v1(-78.74,0) -9.84,68.9 v1(0,68.9) ; v1(807.09,-1200.79) v1(964.57,-1200.79) v1(964.57,-984.25)
  Bottom Layer w50: P1.4 -1624.02,-442.91 -1771.65,-295.28 -1771.65,196.85 -1624.02,344.49 P2.4
INH: R31.2 U12.8 | length 192
  Top Layer w10: R31.2 1119.09,1873.03 1145.47,1846.65 U12.8
LIN: C27.2 P6.2 R37.1 U12.6 | length 516
  Top Layer w10: U12.6 1336.22,1746.65 1336.22,1966.54 R37.1 P6.2
LIN_RX/PA3: J10.9 U1.13 | length 744.2
  Top Layer w10: U1.13 108.27,208.27 J10.9
LIN_TX/PA2: J10.11 U1.12 | length 815.6
  Top Layer w10: U1.12 159.45,159.45 J10.11
NetC1_1: C1.1 U1.5 Y1.2 | length 358.4
  Top Layer w10: U1.5 246.06,-29.53 295.28,-78.74 314.96,-78.74 334.65,-98.43 Y1.2 344.49,-137.8 C1.1
NetC2_1: C2.1 U1.6 Y1.1 | length 338.7
  Top Layer w10: U1.6 265.75,-9.84 285.43,-29.53 Y1.1 ; Y1.1@344.49,-39.37 Y1.1 ; C2.1 452.76,-78.74 403.54,-29.53 Y1.1
NetC3_2: C3.2 U1.3 Y2.3 | length 430.2
  Top Layer w10: U1.3 206.69,-68.9 236.22,-98.43 236.22,-308.07 ; C3.2 236.22,-308.07 ; Y2.3@310.04,-308.07 236.22,-308.07 ; Y2.3 Y2.3@324.02,-320.08
NetC4_2: C4.2 U1.4 Y2.1 | length 491
  Top Layer w10: U1.4 226.38,-49.21 255.91,-78.74 255.91,-157.48 275.59,-177.17 374.02,-177.17 397.64,-200.79 Y2.1 ; Y2.1@398.82,-245.28 Y2.1 ; C4.2 408.46,-233.27 Y2.1
NetC20_2: C20.2 J4.3 R13.2 | length 885.8
  Top Layer w10: C20.2 R13.2 -36.42,1538.39 -100,1474.8 J4.3
NetC21_2: C21.2 J4.5 R15.2 | length 1152.9
  Top Layer w10: R15.2 C21.2 -908.46,1508.46 J4.5
NetC23_2: C23.2 U5.5 | length 93.5
  Top Layer w10: C23.2 889.76,-1331.69 U5.5
NetD1_1: D1.1 P6.3 | length 189.8
  Top Layer w50: D1.1@1306.3,2168.5 P6.3
NetD2_A: D2.A R43.2 | length 163.8
  Top Layer w10: D2.A -1031.3,757.09 R43.2
NetD3_A: D3.A R44.2 | length 319
  Top Layer w10: D3.A -1172.05,698.82 -991.14,698.82 R44.2
NetD4_A: D4.A R45.2 | length 272.1
  Top Layer w10: D4.A -1634.65,757.09 -1555.12,836.61 R45.2
NetD5_A: D5.A R46.2 | length 417.4
  Top Layer w10: D5.A -1762.6,698.82 -1633.86,698.82 -1594.49,738.19 R46.2
NetJ3_1: J3.1 U8.4 | length 390.1
  Top Layer w10: U8.4 -803.35,468.7 -775,440.35 -775,275 J3.1
NetJ3_3: J3.3 U8.2 | length 409.4
  Top Layer w10: U8.2 -821.46,368.7 -800,347.24 -800,148.82 -751.18,100 J3.3
NetJ6_1: J6.1 R22.1 | length 118.4
  Top Layer w10: J6.1 1377.17,-1151.57 R22.1
NetJ6_2: J6.2 R23.2 | length 119.1
  Top Layer w10: J6.2 1375.59,-1251.57 R23.2
NetJ8_1: J8.1 R27.1 | length 118.8
  Top Layer w20: J8.1 -1623.23,1615.94 R27.1
NetJ8_2: J8.2 R28.2 | length 118.7
  Top Layer w20: R28.2 -1526.38,1615.55 J8.2
NetJ9_4: J9.4 R26.2 U6.1 | length 1323.1
  Top Layer w10: U6.1 -1649.8,965.35 R26.2 -1597.44,961.61 v1(-1574.8,984.25)
  Bottom Layer w10: v1(-1574.8,984.25) -1496.06,1062.99 -862.99,1062.99 J9.4
NetJ9_6: J9.6 R25.2 U6.4 | length 1181.7
  Top Layer w10: U6.4 -1499.8,965.35 R25.2 -661.61,961.61 J9.6
NetJ9_8: J9.8 R29.1 U6.2 U6.3 | length 1503.6
  Top Layer w10: U6.2 -1599.8,1136.42 -1574.8,1161.42 -1555.12,1161.42 ; U6.3 -1549.8,1156.1 -1555.12,1161.42 ; R29.1@-1417.32,1161.42 -1555.12,1161.42 ; R29.1 -764.37,1164.37 J9.8
NetJ10_4: J10.4 R35.1 | length 1403.7
  Top Layer w10: J10.4 300,1618.9 433.07,1751.97 R35.1
NetJ10_6: J10.6 R39.2 | length 1017.5
  Top Layer w10: J10.6 400,1187.4 551.18,1338.58 R39.2
NetJ10_10: J10.10 U12.1 | length 1433.3
  Top Layer w10: J10.10 600,1170.87 v1(629.92,1200.79) ; v1(767.72,1200.79) 1122.05,1555.12 1122.05,1791.34 1066.73,1846.65 U12.1
  Bottom Layer w10: v1(629.92,1200.79) v1(767.72,1200.79)
NetJ10_12: J10.12 U12.4 | length 1020.9
  Top Layer w10: J10.12 700,1290.55 1000,1590.55 U12.4
NetJ10_14: J10.14 R31.1 R34.2 | length 1356.7
  Top Layer w10: R34.2 1050,1968.5 ; v1(1050,1925) 1050,1968.5 ; R31.1 1050,1968.5
  Bottom Layer w10: J10.14 800,1100 825,1125 825,1700 v1(1050,1925)
NetJ10_16: J10.16 R41.1 R42.2 | length 1384.2
  Top Layer w10: R42.2 725,1968.5 ; R41.1 725,1968.5 ; v1(900,1600) 800,1600 750,1650 750,1875 725,1900 725,1968.5
  Bottom Layer w10: J10.16 v1(900,1600)
NetQ1_1: Q1.1 R32.1 R33.2 | length 156.2
  Top Layer w10: R33.2 R32.1 847.44,2202.76 Q1.1
NetQ1_3: Q1.3 R37.2 | length 466.2
  Top Layer w20: Q1.3 994.09,2194.88 v1(1043.31,2244.09) ; v1(1220.47,2066.93) 1264.17,2023.23 R37.2
  Bottom Layer w20: v1(1043.31,2244.09) v1(1220.47,2066.93)
NetQ2_1: Q2.1 R35.2 R36.2 | length 156.2
  Top Layer w10: R35.2 R36.2 532.48,2202.76 Q2.1
NetQ2_3: Q2.3 R33.1 | length 75.8
  Top Layer w10: Q2.3 695.87,2148.62 R33.1
NetQ3_1: Q3.1 R39.1 R40.2 | length 156.2
  Top Layer w10: R39.1 R40.2 650.59,1809.05 Q3.1
NetR5_2: R5.2 S3.1 | length 123.5
  Top Layer w10: R5.2 1562.01,561.02 S3.1
NetR7_2: R7.2 S4.1 | length 115.3
  Top Layer w10: R7.2 1574.8,-59.06 1584.65,-68.9 S4.1
NetR10_1: R10.1 U8.6 | length 80
  Top Layer w10: R10.1 -1159.05,418.7 U8.6
NetR11_1: R11.1 U8.5 | length 79.3
  Top Layer w10: R11.1 -1160.63,468.7 U8.5
NetR12_3: R12.3 R13.1 | length 99.6
  Top Layer w10: R13.1 -2.95,1670.28 R12.3
NetR14_3: R14.3 R15.1 | length 99.6
  Top Layer w10: R15.1 -790.35,1670.28 R14.3
NRST: C5.2 J2.6 U1.7 | length 1001.7
  Top Layer w10: U1.7 551.18,9.84 590.55,49.21 590.55,344.49 646.06,400 J2.6 ; C5.2 455.71,6.89
NSLP: J10.8 U12.2 | length 1473.4
  Top Layer w10: J10.8 500,1188.98 v1(688.98,1377.95) v1@688.98,1368.11 ; v1(767.72,1299.21) 1082.68,1614.17 1082.68,1771.65 1057.68,1796.65 U12.2
  Bottom Layer w10: v1(688.98,1377.95) v1(767.72,1299.21)
NWAKE: Q3.3 R38.1 U12.3 | length 213.1
  Top Layer w10: Q3.3 813.98,1754.92 R38.1 922.24,1754.92 930.51,1746.65 U12.3
NWE: J1.1 R2.1 U3.7 | length 362.4
  Top Layer w10: U3.7 v1(-182.48,-1043.31) R2.1@-182.48,-1006.3
  Bottom Layer w10: J1.1 -200,-1025.79 v1(-182.48,-1043.31)
PA1: J10.13 J10.15 U1.11 | length 1005.3
  Top Layer w10: U1.11 160.62,89.76 207.87,89.76 216.54,98.43 216.54,118.11 798.43,700 J10.13 J10.15
PA4: J10.7 U1.14 | length 711
  Top Layer w10: U1.14 88.58,288.58 J10.7
PA5: J10.5 U1.15 | length 677.7
  Top Layer w10: U1.15 68.9,368.9 J10.5
PA6: J10.3 U1.16 | length 644.4
  Top Layer w10: U1.16 49.21,449.21 J10.3
PA7: J10.1 U1.17 | length 611.2
  Top Layer w10: U1.17 29.53,529.53 J10.1
PA8: U1.29
PB2: J9.7 U1.20 | length 783.5
  Top Layer w10: J9.7 -310.24,610.24 -157.48,610.24 -29.53,482.28 U1.20
PB12: J13.1 R43.1 U1.25 | length 1125.4
  Top Layer w10: R43.1 -875.98,836.61 -836.61,797.24 -836.61,736.61 J13.1 -525,425 -525,375 -258.27,108.27 U1.25
PB13: J13.2 R44.1 U1.26 | length 1086.8
  Top Layer w10: R44.1 -888.19,738.19 v1(-850,700) ; J13.2 -600,399.54 -289.04,88.58 U1.26
  Bottom Layer w10: v1(-850,700) -725,575 -675,575 -650,550 -650,450 J13.2
PB14: J13.3 R45.1 U1.27 | length 1627.6
  Top Layer w10: R45.1 -1243.11,669.29 -869.29,669.29 J13.3 -650,450 -650,350 -625,325 -575,325 -318.9,68.9 U1.27
PB15: J13.4 R46.1 U1.28 | length 1580.3
  Top Layer w10: R46.1 -1312.01,639.76 -939.76,639.76 J13.4 -700,325 -650,275 -575,275 -349.21,49.21 U1.28
RESET: J2.5 S2.1 | length 807.5
  Top Layer w10: J2.5 1273.23,400 1427.17,246.06 S2.1
S: J7.5 R20.1 U5.8 | length 627.3
  Top Layer w10: J7.5 500,-874.02 610.24,-984.25 767.72,-984.25 787.4,-984.25 804.13,-1000.98 R20.1 866.14,-1043.31 889.76,-1066.93 U5.8
SCK: J5.3 P3.5 R18.1 U4.6 | length 1361.1
  Top Layer w10: P3.5 -1354.33,-1224.41 -1338.58,-1240.16 R18.1 ; v2(-1082.68,-1279.53) -1082.68,-1222.44 U4.6
  Bottom Layer w10: v2(-1279.53,-1240.16) -1240.16,-1279.53 v2(-1082.68,-1279.53) -923.62,-1279.53 -600,-955.91 J5.3
SCL: J1.3 R3.1 U3.6 | length 373.9
  Top Layer w10: U3.6 -132.48,-1057.68 v1(-118.11,-1043.31) R3.1
  Bottom Layer w10: v1(-118.11,-1043.31) -100,-1025.2 J1.3
SDA: J1.5 P7.2 R4.1 U3.5 | length 644.5
  Top Layer w10: R4.1 v1(-59.06,-1043.31) -82.48,-1066.73 U3.5 -82.48,-1177.36 -59.06,-1200.79 P7.2
  Bottom Layer w10: v1(-59.06,-1043.31) 0,-984.25 J1.5
SPI_MISO/PB4: J5.6 U1.40 | length 738.8
  Top Layer w10: J5.6 -500,-696.85 -433.07,-629.92 -413.39,-629.92 -49.21,-265.75 U1.40
SPI_MOSI/PB5: J5.8 U1.41 | length 694
  Top Layer w10: J5.8 -400,-655.91 -29.53,-285.43 U1.41
SPI_NSS/PA15: J5.2 U1.38 | length 874.5
  Top Layer w10: J5.2 -590.55,-590.55 -452.76,-590.55 -88.58,-226.38 U1.38
SPI_SCK/PB3: J5.4 U1.39 | length 805.7
  Top Layer w10: J5.4 -510.24,-610.24 -433.07,-610.24 -68.9,-246.06 U1.39
SWCLK/PA14: pad.1 U1.37 | length 278.5
  Top Layer w10: pad.1 -200,-300 -108.27,-208.27 U1.37
SWDIO/PA13: pad.0 U1.34 | length 453.4
  Top Layer w10: pad.0 -550,-100 -518.9,-68.9 U1.34
V5_485: C24.2 J9.2 R25.1 R26.1 R30.1 U6.8 U10.5 | length 2284.1
  Top Layer w10: U6.8 -1649.8,1224.21 -1676.18,1197.83 C24.2 -1774.61,1197.83 -1791.34,1181.1 -1791.34,984.25 -1735.24,928.15 R26.1 R25.1 -828.15,928.15 J9.2 ; v1(-1574.8,1358.27) U10.5 ; v1(-1377.95,1594.49) R30.1
  Top Layer w20: C24.2 v1(-1732.28,1279.53)
  Bottom Layer w20: v1(-1732.28,1279.53) -1653.54,1279.53 v1(-1574.8,1358.27) -1377.95,1555.12 v1(-1377.95,1594.49)
V5_CAN: C22.2 J7.6 J7.7 R21.1 U5.3 U9.5 | length 1501.6
  Top Layer w10: J7.6 J7.7 ; R21.1 573.82,-1203.74 595.87,-1225.79 U5.3 753.35,-1225.79 767.72,-1240.16 v1(767.72,-1259.84) ; U9.5 v1(1200.79,-1200.79)
  Bottom Layer w10: J7.7 767.72,-967.72 v1(767.72,-1259.84) 1141.73,-1259.84 v1(1200.79,-1200.79)
V5_LIN: C26.2 C28.2 C29.1 C30.1 C31.1 C32.2 J12.1 U11.3 | length 865
  Top Layer w20: J12.1 1216.14,816.14 C30.1 C31.1 C28.2 C29.1 C32.2 ; C31.1@1221.6,1088.14 U11.3 1378.12,1032.51 C26.2
V5_USB: C17.2 J7.8 J9.1 J12.2 P1.1 P2.1 U2.3 U7.5 U8.7 | length 6577.4
  Top Layer w10: v2(-1574.8,0) U7.5 ; v2(-1279.53,295.28) -1244.49,330.32 C17.2 -1142.72,368.7 U8.7
  Top Layer w50: v2(-1161.42,-177.17) U2.3
  Bottom Layer w10: -1328.74,344.49 -923.23,750 -700,750 ; -1279.53,-393.7 -923.23,-750 550,-750 J7.8 ; J9.1 -700,750 ; J12.2 1100,700 1050,750 -700,750
  Bottom Layer w50: v2(-1574.8,0) -1279.53,0 ; P1.1 -1328.74,-442.91 -1279.53,-393.7 -1279.53,-177.17 ; P2.1 -1328.74,344.49 v2(-1279.53,295.28) -1279.53,0 ; v2(-1161.42,-177.17) -1279.53,-177.17 ; -1279.53,-177.17 -1279.53,0
V12_LIN: C25.2 D1.2 Q1.2 R32.2 R38.2 R41.2 U11.1 U12.7 | length 1919.8
  Top Layer w10: R32.2 847.44,2127.95 Q1.2
  Top Layer w20: R41.2 842.13,1968.5 ; R38.2 866.14,1944.49 842.13,1968.5 ; Q1.2 948.62,2075 ; D1.2 D1.2@1137.8,2162.8 ; U12.7 1271.65,1796.65 v1(1300,1825) 1300,1875 1275,1900 1225,1900 1175,1950 1175,2025 1137.8,2062.2 D1.2@1137.8,2162.8 ; v1(1375,1500) 1421.65,1453.35 C25.2 1377.95,1334.25 U11.1 ; 842.13,1968.5 948.62,2075 ; 948.62,2075 1050,2075 D1.2@1137.8,2162.8
  Bottom Layer w20: v1(1300,1825) 1300,1575 v1(1375,1500)
V33: C18.2 C19.2 J11.1 J11.3 J11.5 P3.4 R16.2 R17.2 R18.2 R19.2 U2.2 U4.5 | length 3030.5
  Top Layer w10: R19.2 R18.2 -1164.37,-1181.1 ; R16.2 R17.2 -1164.37,-1181.1 ; U4.5 -1164.37,-1181.1 ; C18.2 -825,-555.51 ; J11.1 J11.3 J11.5 -755.51,-555.51 -825,-555.51 ; -1164.37,-1181.1 P3.4 -1543.9,-1181.1 -1575,-1150 -1575,-925 -1400,-750 -1250,-750 -1125,-875 -925,-875 -825,-775 -825,-555.51
  Top Layer w50: C19.2 -984.25,-555.51 ; U2.2@-984.25,-177.17 -984.25,-413.39 -984.25,-555.51 ; C18.2 -984.25,-555.51
V33_EEP: C13.2 J1.7 P7.3 R2.2 R3.2 R4.2 U3.1 U3.2 U3.8 | length 1259.7
  Top Layer w10: U3.2 -182.48,-1409.06 C13.2 -216.54,-1417.32 -232.48,-1401.38 U3.1 U3.8 -232.48,-987.99 -212.01,-967.52 R2.2 R3.2 R4.2 56.1,-967.52 ; P7.3 98.43,-1009.84 56.1,-967.52 ; J1.7 100,-923.62 56.1,-967.52
V33_POT: J4.1 R12.2 R14.2 | length 1807.4
  Top Layer w10: R14.2 -531.5,1771.65 59.06,1771.65 R12.2 157.48,1437.01 0,1279.53 J4.1
V33_USB: C16.2 R9.2 U8.3 U8.8 | length 705.1
  Top Layer w10: R9.2 -1023.62,531.5 -984.25,492.13 -984.25,334.65 -1000.2,318.7 U8.8 -1086.61,269.68 -1062.99,246.06 C16.2 ; -979.72,418.7 U8.3
VBAT: BT1.1 U1.1 | length 956.9
  Top Layer w10: v1(157.48,-196.85) 157.48,-110.24 U1.1 ; v1(885.83,-196.85) BT1.1@984.25,-98.43
  Bottom Layer w10: v1(157.48,-196.85) v1(885.83,-196.85)
VDD: C6.2 C7.2 C8.2 C9.2 C10.2 J1.8 J4.2 J11.2 J11.4 J11.6 L1.1 S1.2 S3.2 S4.2 U1.24 U1.36 U1.48 | length 5843.6
  Top Layer w10: J11.6 J11.4 J11.2 -468.11,-168.11 C9.2 -328.54,-168.11 C6.2 -252.95,-134.84 -226.38,-108.27 U1.36 -108.27,-108.27 v1(0,0) ; v1(-175,450) -175,380.91 C10.2 -168.11,328.54 C8.2 -134.84,252.95 -108.27,226.38 U1.24 -108.27,108.27 v1(0,0) ; C7.2@108.27,-288.39 U1.48 108.27,-108.27 v1(0,0) ; v1(433.07,49.21) 491.34,49.21 L1.1
  Bottom Layer w10: J11.6 -1.97,-500 100,-601.97 J1.8 ; v1(-175,450) -175,525 J4.2 ; v1(0,0) 49.21,49.21 v1(433.07,49.21) 1131.89,49.21 ; S1.2 1427.17,-344.49 1427.17,-246.06 ; S4.2 1427.17,-246.06 ; S3.2 1466.54,383.86 1131.89,49.21 ; 1131.89,49.21 1427.17,-246.06
VDDA: C11.1 C12.1 L1.2 U1.9 | length 357.5
  Top Layer w10: U1.9 246.06,49.21 272.64,75.79 C11.1 328.54,109.06 L1.2
WK1: C14.2 J2.7 R5.1 R6.2 | length 769.5
  Top Layer w10: J2.7 1366.14,500 1397.64,531.5 R5.1 C14.2
WK2: C15.2 J2.3 R7.1 R8.2 | length 905.2
  Top Layer w10: J2.3 1139.96,300 R7.1 C15.2
WKUP1/PA0: J2.8 U1.10 | length 819.1
  Top Layer w10: U1.10 226.38,68.9 657.48,500 J2.8
WKUP2/PC13: J2.4 U1.2 | length 1103.1
  Top Layer w10: U1.2 196.85,-88.58 216.54,-108.27 216.54,-127.95 v1(196.85,-147.64) ; v1(590.55,-147.64) 639.76,-98.43 639.76,246.06 693.7,300 J2.4
  Bottom Layer w10: v1(196.85,-147.64) v1(590.55,-147.64)
pads on no net: J10.2 P1.5 P1.6 P2.5 P2.6 P3.0 P3.1 P3.8 R12.0 R14.0 S1.3 S1.4 S2.3 S2.4 S3.3 S3.4 S4.3 S4.4 Y2.2 Y2.4

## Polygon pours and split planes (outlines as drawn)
GND on Top Layer "Top Layer-GND" (hatched 45Degree grid 20 track 8, remove dead copper, pour order 6): -1968.5,-1574.8 -1968.5,2362.2 1968.5,2362.2 1968.5,-1574.8
GND on Bottom Layer "Top Layer-GND" (hatched 45Degree grid 20 track 8, remove dead copper, pour order 8): -1968.5,-1574.8 -1968.5,2362.2 1968.5,2362.2 1968.5,-1574.8

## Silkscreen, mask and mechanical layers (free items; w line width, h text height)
Top Overlay:
  text "LIN (TJA1020)" at 1299.21,1496.06 h100
  text "www.github.com/taoynkkx/STM32F0_Platform" at -1181.1,1377.95 h100
  text "STM32F072 Platform A0" at -1181.1,1181.1 h180
  text "2018.07.22" at 275.59,1062.99 h100
  text "RS485" at -1417.32,1023.62 h100
  text "V4" at -725,875 h40
  text "RO" at -625,875 h40
  text "DI" at -525,875 h40
  text "DE" at -425,875 h40
  text "P2" at -225,875 h40
  text "P1" at -125,875 h40
  text "P1" at -125,875 h40
  text "VP" at -25,875 h40
  text "NC" at 175,875 h40
  text "MS" at 275,875 h40
  text "NW" at 375,875 h40
  text "NS" at 475,875 h40
  text "RX" at 575,875 h40
  text "TX" at 675,875 h40
  text "INH" at 775,875 h40
  text "VS" at 925,875 h40
  text "VL" at 1275,775 h40
  text "VU" at 1275,675 h40
  text "VU" at -750,600 h40
  text "B11" at -650,600 h40
  text "B10" at -525,600 h40
  text "B2" at -400,600 h40
  text "B1" at -225,600 h40
  text "B0" at -125,600 h40
  text "VD" at -25,600 h40
  text "A7" at 175,600 h40
  text "A6" at 275,600 h40
  text "A5" at 375,600 h40
  text "A4" at 475,600 h40
  text "A3" at 575,600 h40
  text "A2" at 675,600 h40
  text "A1" at 775,600 h40
  text "A1" at 875,600 h40
  text "B14" at -875,525 h40
  text "B12" at -525,475 h40
  text "A0" at 650,475 h40
  text "WK1" at 975,475 h40
  text "B13" at -525,375 h40
  text "RST" at 625,375 h40
  text "RST" at 975,375 h40
  text "B15" at -750,300 h40
  text "C13" at 625,275 h40
  text "WK2" at 975,275 h40
  text "A9" at -525,175 h40
  text "BT0" at 625,175 h40
  text "BT0" at 975,175 h40
  text "UART" at -1929.13,78.74 h100
  text "A10" at -525,75 h40
  text "SWD/A13" at -750,-200 h40
  text "SWC/A14" at -425,-250 h40
  text "V3" at -825,-325 h40
  text "VD" at -525,-325 h40
  text "V3" at -825,-425 h40
  text "VD" at -525,-425 h40
  text "V3" at -825,-525 h40
  text "VD" at -525,-525 h40
  text "A15" at -775,-625 h40
  text "B3" at -625,-625 h40
  text "B4" at -525,-625 h40
  text "B5" at -425,-625 h40
  text "GND" at -275,-625 h40
  text "B6" at -125,-625 h40
  text "B7" at -25,-625 h40
  text "VD" at 75,-625 h40
  text "B8" at 275,-625 h40
  text "B9" at 375,-625 h40
  text "VC" at 475,-625 h40
  text "VU" at 575,-625 h40
  text "USB" at -1929.13,-708.66 h100
  text "CS" at -725,-900 h40
  text "CK" at -625,-900 h40
  text "DO" at -525,-900 h40
  text "DI" at -425,-900 h40
  text "WP" at -225,-900 h40
  text "CL" at -125,-900 h40
  text "DA" at -25,-900 h40
  text "VE" at 75,-900 h40
  text "RX" at 275,-900 h40
  text "TX" at 375,-900 h40
  text "S" at 475,-900 h40
  text "VC" at 575,-900 h40
  text "TF Card (SPI)" at -1259.84,-1496.06 h100
  text "AT24 + 18B20" at -78.74,-1496.06 h100
  text "CAN (TJA1050)" at 708.66,-1496.06 h100
Mechanical 1:
  the board outline again, w7.87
